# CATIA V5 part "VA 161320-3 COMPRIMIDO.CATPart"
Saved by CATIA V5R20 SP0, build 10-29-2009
Part number: VA 161320-3 COMPRIMIDO
Revision: ANY
Definition: UNKNOWN
Nomenclature: VA 161320-3 COMPRIMIDO
Source: Unknown
Bounding box of the stored display mesh (mm): x -5.25 to 5.25, y 0 to 5.8, z -5.25 to 5.25
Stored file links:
  C:\Users\Utente\Desktop\IO LAVORO\3D X SITO CF\CUMSA\3D files VA\VA 161320\VA 161320-3 COMPRIMIDO.CATPart
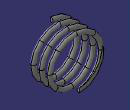
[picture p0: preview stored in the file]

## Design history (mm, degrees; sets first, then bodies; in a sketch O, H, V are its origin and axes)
Body1 "Cortar-Extruir1" (main body)
  Solid1: solid without history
